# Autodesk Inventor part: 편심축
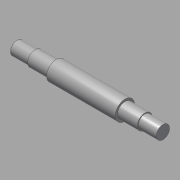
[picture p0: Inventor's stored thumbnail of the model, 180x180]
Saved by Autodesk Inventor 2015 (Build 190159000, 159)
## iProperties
Created: 2015-10
Part Number: 편심축
Document SubType Name: Modeling
Designer: mdu
Density: 7.86 g/cm^3
Material: 강철, 연강
Mass: 1163.82 g
Surface Area: 210.981 cm^2
Volume: 148.069 cm^3
Appearance: 강철
Author: mdu
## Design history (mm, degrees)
sketch "스케치1"
  geometry: L1 (-20.5, -41.331)-(-20.5, 32.669) reference; L2 (7.5, -30.031)-(7.5, 21.369) reference; L3 (135.5, -30.331)-(135.5, 21.669) reference; L4 (121.5, 21.369)-(121.5, -30.031) reference; L5 (184.5, -4.331)-(-7.5, -4.331); L6 (184.5, -4.331)-(184.5, 6.669); L7 (154.5, 8.169)-(121.5, 8.169); L8 (121.5, 8.169)-(121.5, 11.669); L9 (121.5, 11.669)-(7.5, 11.669); L10 (7.5, 11.669)-(7.5, 8.169); L11 (7.5, 8.169)-(-7.5, 8.169); L12 (-7.5, 8.169)-(-7.5, -4.331); L13 (154.5, 8.169)-(154.5, 6.669); L14 (154.5, 6.669)-(184.5, 6.669); C1 r 32.5 at (64.5, -4.331) reference; 1 further point
  constraints: 21 end point, 8 perpendicular, 5 point on line, 1 collinear
  dimensions: "d1" = 25 diameter of L11 L5; "d2" = 32 diameter of L9 L5; "d4" = 15 distance of L10.end L11.end; "d15" = 33 distance of L7.start L7.end; "d26" = 30 distance of L13.end L6.end; "d36" = 22 diameter of L14 L5
revolve "회전1" sketch "스케치1" stored, may be unused: angle "d6" = 90 deg
node "작업 평면1"
sketch "스케치2"
  geometry: C1 r 16 at (0, 0) reference; C2 r 20.75 at (0, 4)
  constraints: 1 centre point, 1 vertical alignment
  dimensions: "d34" = 4 distance of C2.centre C1.centre; "d35" = 41.5 diameter of C2
extrude "돌출1" join sketch "스케치2" stored distance "d9" = 40; taper "d10" = 0 deg
chamfer "모따기1" distance "d11" = 1; stored, may be unused: second distance "d12" = 2, angle "d13" = 45 deg
node "작업 평면2"
sketch "스케치3"
  geometry: L1 (-15, -10)-(-15, 10) reference; L2 (-15, 3)-(0, 3); L3 (0, -3)-(-15, -3); A1 r 3 centre (0, 0) between (0, -3) and (0, 3); 2 further points
  constraints: 4 end point, 2 perpendicular, 2 point on circle, 2 point on line, 2 tangent, 1 centre point, 1 horizontal alignment, 1 midpoint
  dimensions: "d16" = 18 dimension on A1 L1; "d17" = 6 distance between parallel lines of L3 L2
extrude "돌출2" cut sketch "스케치3" distance "d18" = 3.5; taper "d19" = 0 deg
node "솔리드1"
node "참조1"
node "참조2"
node "참조3"
node "참조4"
node "참조5"
other parameters: "d30" = 35
